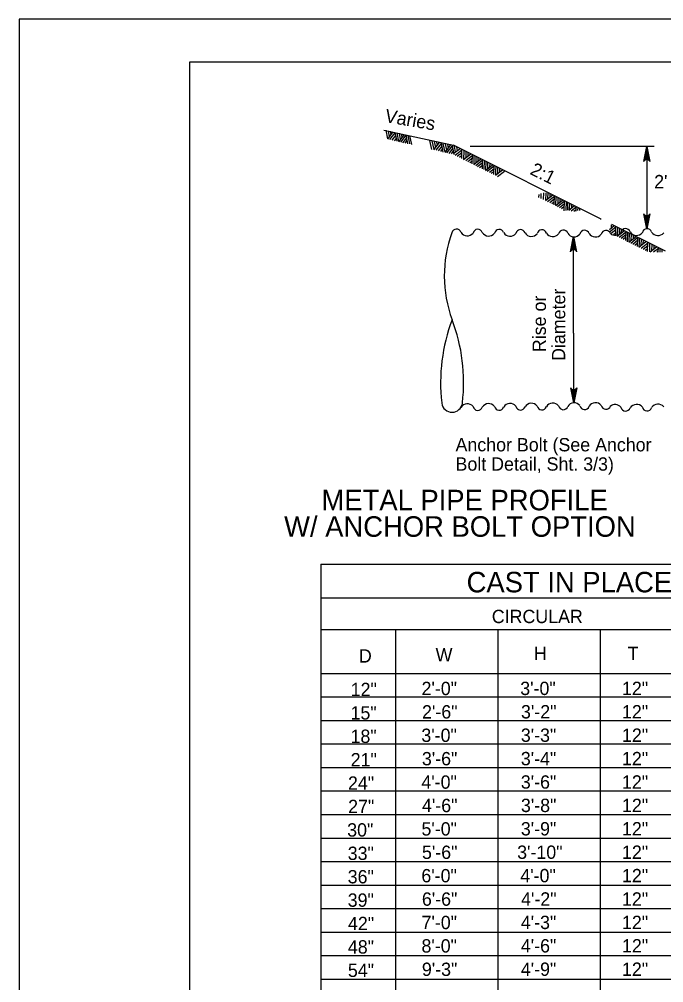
# Model space of a CAD drawing. Extents: x 1083.1 to 1117.1, y 675.4 to 741.4.
# Drawn here: x 1083.13 to 1090.68, y 730.07 to 741.35 of the extents above; entities that cross this region are included whole.
import ezdxf

# ---------------------------------------------------------------- set-up
doc = ezdxf.new("R2010")
doc.units = 0
doc.layers.add('Level 1', color=7, linetype='Continuous')

msp = doc.modelspace()

# ---------------------------------------------------------------- linework, layer by layer
at = {"layer": 'Level 1'}
for p, q in [((1087.399, 740.054), (1088.214, 739.88)), ((1087.444, 739.953), (1087.423, 740.054)), ((1087.443, 739.951), (1087.508, 740.035)), ((1087.465, 739.979), (1087.45, 740.048)), ((1087.469, 739.945), (1087.531, 740.025)), ((1087.483, 740.004), (1087.476, 740.042)), ((1087.552, 739.925), (1087.53, 740.03)), ((1087.574, 739.923), (1087.553, 740.024)), ((1087.572, 739.921), (1087.638, 740.005)), ((1087.593, 739.948), (1087.579, 740.019)), ((1087.613, 739.973), (1087.605, 740.012)), ((1087.495, 739.938), (1087.538, 739.993)), ((1087.523, 739.932), (1087.545, 739.96)), ((1087.596, 739.915), (1087.659, 739.997)), ((1087.621, 739.909), (1087.665, 739.967)), ((1087.646, 739.904), (1087.672, 739.937)), ((1087.68, 739.896), (1087.659, 740)), ((1087.703, 739.894), (1087.682, 739.995)), ((1087.724, 739.889), (1087.702, 739.99)), ((1087.96, 739.831), (1087.937, 739.936)), ((1087.986, 739.828), (1087.965, 739.929)), ((1087.984, 739.826), (1088.049, 739.91)), ((1088.006, 739.854), (1087.992, 739.923)), ((1088.01, 739.82), (1088.072, 739.9)), ((1088.025, 739.879), (1088.017, 739.917)), ((1088.094, 739.8), (1088.071, 739.905)), ((1088.116, 739.798), (1088.094, 739.899)), ((1088.135, 739.823), (1088.12, 739.894)), ((1088.037, 739.813), (1088.079, 739.868)), ((1088.065, 739.807), (1088.086, 739.835)), ((1088.114, 739.796), (1088.179, 739.88)), ((1088.137, 739.79), (1088.2, 739.872)), ((1088.154, 739.848), (1088.146, 739.887)), ((1088.163, 739.784), (1088.207, 739.842)), ((1088.188, 739.779), (1088.213, 739.812)), ((1088.222, 739.771), (1088.2, 739.875)), ((1089.944, 739.015), (1088.214, 739.88)), ((1088.219, 739.785), (1088.29, 739.842)), ((1088.238, 739.8), (1088.224, 739.87)), ((1088.233, 739.762), (1088.312, 739.826)), ((1088.262, 739.819), (1088.254, 739.86)), ((1088.257, 739.75), (1088.312, 739.793)), ((1088.31, 739.724), (1088.312, 739.831)), ((1088.332, 739.713), (1088.415, 739.779)), ((1088.334, 739.714), (1088.337, 739.818)), ((1088.36, 739.735), (1088.362, 739.806)), ((1088.384, 739.755), (1088.385, 739.794)), ((1090.562, 739.865), (1088.41, 739.865)), ((1090.454, 739.703), (1090.478, 739.865)), ((1090.464, 739.709), (1090.478, 739.865)), ((1090.478, 739.865), (1090.478, 738.9)), ((1090.478, 739.712), (1090.478, 739.865)), ((1090.49, 739.71), (1090.478, 739.865)), ((1090.501, 739.705), (1090.478, 739.865)), ((1088.282, 739.738), (1088.311, 739.761)), ((1088.356, 739.701), (1088.435, 739.764)), ((1088.381, 739.688), (1088.435, 739.732)), ((1088.406, 739.676), (1088.434, 739.698)), ((1088.433, 739.662), (1088.436, 739.769)), ((1088.451, 739.653), (1088.534, 739.72)), ((1088.454, 739.655), (1088.457, 739.759)), ((1088.473, 739.642), (1088.553, 739.707)), ((1088.478, 739.674), (1088.48, 739.747)), ((1088.496, 739.631), (1088.553, 739.676)), ((1088.503, 739.694), (1088.504, 739.735)), ((1088.551, 739.603), (1088.554, 739.71)), ((1088.572, 739.595), (1088.575, 739.699)), ((1088.591, 739.587), (1088.594, 739.69)), ((1088.615, 739.606), (1088.617, 739.678)), ((1088.64, 739.626), (1088.641, 739.666)), ((1088.519, 739.619), (1088.552, 739.646)), ((1088.588, 739.585), (1088.671, 739.651)), ((1088.609, 739.574), (1088.69, 739.639)), ((1088.633, 739.562), (1088.689, 739.607)), ((1088.656, 739.551), (1088.689, 739.577)), ((1088.687, 739.535), (1088.691, 739.642)), ((1088.704, 739.527), (1088.787, 739.593)), ((1088.709, 739.531), (1088.71, 739.581)), ((1088.71, 739.581), (1088.712, 739.631)), ((1088.73, 739.514), (1088.809, 739.577)), ((1088.731, 739.549), (1088.733, 739.62)), ((1088.755, 739.568), (1088.757, 739.608)), ((1089.214, 739.269), (1089.215, 739.301)), ((1089.241, 739.256), (1089.242, 739.314)), ((1089.267, 739.245), (1089.27, 739.321)), ((1089.292, 739.233), (1089.375, 739.299)), ((1089.294, 739.235), (1089.297, 739.322)), ((1089.316, 739.221), (1089.395, 739.284)), ((1089.32, 739.255), (1089.322, 739.32)), ((1089.34, 739.209), (1089.394, 739.252)), ((1089.344, 739.275), (1089.345, 739.314)), ((1089.366, 739.196), (1089.393, 739.218)), ((1089.393, 739.183), (1089.395, 739.289)), ((1089.411, 739.173), (1089.494, 739.24)), ((1089.413, 739.175), (1089.417, 739.279)), ((1089.432, 739.163), (1089.513, 739.227)), ((1089.438, 739.195), (1089.44, 739.267)), ((1089.463, 739.215), (1089.464, 739.255)), ((1089.51, 739.111), (1089.513, 739.23)), ((1089.532, 739.116), (1089.535, 739.219)), ((1089.456, 739.151), (1089.512, 739.196)), ((1089.479, 739.139), (1089.511, 739.166)), ((1089.551, 739.119), (1089.553, 739.21)), ((1089.565, 739.119), (1089.631, 739.172)), ((1089.574, 739.126), (1089.577, 739.198)), ((1089.591, 739.112), (1089.65, 739.159)), ((1089.6, 739.146), (1089.601, 739.187)), ((1089.624, 739.108), (1089.649, 739.128)), ((1089.649, 739.109), (1089.65, 739.162)), ((1089.671, 739.114), (1089.672, 739.151)), ((1089.692, 739.116), (1089.693, 739.14)), ((1089.94, 739.009), (1089.94, 739.017)), ((1090.456, 739.061), (1090.478, 738.9)), ((1090.467, 739.055), (1090.478, 738.9)), ((1090.503, 739.063), (1090.478, 738.9)), ((1090.493, 739.056), (1090.478, 738.9)), ((1090.478, 739.054), (1090.478, 738.9)), ((1090.039, 738.894), (1090.096, 738.939)), ((1090.04, 738.864), (1090.116, 738.924)), ((1090.041, 738.895), (1090.041, 738.897)), ((1090.041, 738.897), (1090.041, 738.897)), ((1090.061, 738.848), (1090.115, 738.891)), ((1090.064, 738.915), (1090.066, 738.947)), ((1090.066, 738.947), (1090.066, 738.947)), ((1090.698, 738.638), (1090.069, 738.953)), ((1090.113, 738.822), (1090.116, 738.929)), ((1090.131, 738.813), (1090.215, 738.88)), ((1090.134, 738.815), (1090.137, 738.918)), ((1090.158, 738.834), (1090.16, 738.907)), ((1090.183, 738.854), (1090.185, 738.895)), ((1089.595, 738.648), (1089.62, 738.81)), ((1089.606, 738.654), (1089.62, 738.81)), ((1089.62, 738.657), (1089.62, 738.81)), ((1089.631, 738.655), (1089.62, 738.81)), ((1089.642, 738.65), (1089.62, 738.81)), ((1089.62, 737.68), (1089.62, 738.807)), ((1090.086, 738.836), (1090.114, 738.858)), ((1090.153, 738.802), (1090.234, 738.867)), ((1090.177, 738.791), (1090.233, 738.836)), ((1090.199, 738.779), (1090.232, 738.805)), ((1090.231, 738.763), (1090.234, 738.87)), ((1090.252, 738.748), (1090.255, 738.854)), ((1090.268, 738.745), (1090.352, 738.811)), ((1090.271, 738.747), (1090.274, 738.85)), ((1090.29, 738.734), (1090.37, 738.798)), ((1090.295, 738.766), (1090.297, 738.838)), ((1090.313, 738.722), (1090.37, 738.767)), ((1090.32, 738.786), (1090.322, 738.826)), ((1090.368, 738.695), (1090.371, 738.801)), ((1090.391, 738.741), (1090.392, 738.791)), ((1090.412, 738.708), (1090.414, 738.78)), ((1090.436, 738.728), (1090.437, 738.768)), ((1090.336, 738.711), (1090.369, 738.737)), ((1090.384, 738.687), (1090.468, 738.753)), ((1090.389, 738.691), (1090.391, 738.741)), ((1090.41, 738.674), (1090.49, 738.737)), ((1090.435, 738.661), (1090.489, 738.704)), ((1090.459, 738.649), (1090.488, 738.672)), ((1090.487, 738.635), (1090.49, 738.742)), ((1090.512, 738.631), (1090.515, 738.73)), ((1090.518, 738.631), (1090.593, 738.69)), ((1090.538, 738.647), (1090.54, 738.717)), ((1090.555, 738.63), (1090.613, 738.675)), ((1090.562, 738.666), (1090.563, 738.705)), ((1090.612, 738.628), (1090.613, 738.68)), ((1090.633, 738.627), (1090.634, 738.67)), ((1090.657, 738.627), (1090.658, 738.658)), ((1090.594, 738.629), (1090.612, 738.643)), ((1089.62, 737.68), (1089.62, 736.862)), ((1089.6, 737.022), (1089.622, 736.862)), ((1089.611, 737.017), (1089.622, 736.862)), ((1089.647, 737.024), (1089.622, 736.862)), ((1089.636, 737.018), (1089.622, 736.862)), ((1089.622, 737.015), (1089.622, 736.862)), ((1086.66, 734.976), (1086.654, 720.144)), ((1086.66, 734.976), (1103.868, 734.976)), ((1103.868, 734.576), (1086.654, 734.576)), ((1103.868, 734.205), (1086.654, 734.205)), ((1087.536, 721.026), (1087.536, 734.205)), ((1088.735, 721.026), (1088.735, 734.205)), ((1089.935, 721.026), (1089.935, 734.205)), ((1103.868, 733.692), (1086.654, 733.692)), ((1103.868, 733.692), (1086.689, 733.692)), ((1103.868, 733.416), (1086.654, 733.416)), ((1103.868, 733.141), (1086.654, 733.141)), ((1103.868, 732.865), (1086.654, 732.865)), ((1103.868, 732.59), (1086.654, 732.59)), ((1103.868, 732.315), (1086.654, 732.315)), ((1103.868, 732.039), (1086.654, 732.039)), ((1103.868, 731.764), (1086.654, 731.764)), ((1103.868, 731.489), (1086.654, 731.489)), ((1103.868, 731.213), (1086.654, 731.213)), ((1097.894, 730.938), (1086.654, 730.938)), ((1097.894, 730.663), (1086.654, 730.663)), ((1103.868, 730.387), (1086.654, 730.387)), ((1091.981, 730.112), (1086.654, 730.112))]:
    msp.add_line(p, q, dxfattribs=at)
for points in [[(1083.126, 719.354), (1117.126, 719.354), (1117.126, 741.354), (1083.126, 741.354)], [(1085.126, 740.854), (1116.626, 740.854), (1116.626, 719.854), (1085.126, 719.854)]]:
    msp.add_lwpolyline(points, close=True, dxfattribs=at)
for points in [[(1090.443, 739.688), (1090.478, 739.865), (1090.514, 739.688)], [(1090.514, 739.077), (1090.478, 738.9), (1090.443, 739.077)], [(1089.585, 738.633), (1089.62, 738.81), (1089.655, 738.633)], [(1089.657, 737.039), (1089.622, 736.862), (1089.587, 737.039)]]:
    msp.add_lwpolyline(points, dxfattribs=at)
for centre, start, end in [((1090.478, 739.674), 22.0878, 157.9139), ((1090.478, 739.092), 202.0878, 337.9139), ((1089.62, 738.619), 22.0878, 157.9139), ((1089.622, 737.054), 202.0878, 337.9139)]:
    msp.add_arc(centre, 0.0382, start, end, dxfattribs=at)
for centre, major_axis, start_param, end_param in [((1088.248, 738.841), (0.056, 0), 0.338176, 2.886862), ((1088.498, 738.839), (0.056, 0), 0.338176, 2.936471), ((1088.748, 738.837), (0.056, 0), 0.338176, 2.936471), ((1088.998, 738.835), (0.056, 0), 0.338176, 2.936471), ((1089.248, 738.833), (0.056, 0), 0.338176, 2.936471), ((1089.499, 738.83), (0.056, 0), 0.338176, 2.936471), ((1089.749, 738.828), (0.056, 0), 0.338176, 2.936471), ((1089.999, 738.826), (0.056, 0), 0.338176, 2.936471), ((1090.23, 738.847), (0.056, 0), 0.338176, 2.936471), ((1090.481, 738.845), (0.056, 0), 0.338176, 2.936471), ((1089.598, 738.35), (-1.493, 0), 5.937722, 6.635502), ((1088.375, 738.906), (0.0877, 0), 3.693284, 5.600053), ((1088.625, 738.904), (0.0877, 0), 3.693284, 5.600053), ((1088.876, 738.902), (0.0877, 0), 3.693284, 5.600053), ((1089.126, 738.899), (0.0877, 0), 3.693284, 5.600053), ((1089.376, 738.897), (0.0877, 0), 3.693284, 5.600053), ((1089.626, 738.895), (0.0877, 0), 3.693284, 5.600053), ((1089.876, 738.893), (0.0877, 0), 3.693284, 5.600053), ((1090.107, 738.913), (0.0877, 0), 4.01572, 5.600053), ((1090.358, 738.911), (0.0877, 0), 3.693284, 5.600053), ((1090.608, 738.909), (0.0877, 0), 3.693284, 5.600053), ((1090.127, 737.101), (-2.065, 0), 5.919813, 6.398853), ((1086.267, 737.101), (2.065, 0), 6.167517, 6.646557), ((1088.197, 736.875), (-0.122, 0), 0.132192, 1.570796), ((1088.197, 736.875), (0.122, 0), 4.712389, 6.150994), ((1088.375, 736.764), (0.0877, 0), 0.683132, 2.589902), ((1088.625, 736.766), (0.0877, 0), 0.683132, 2.589902), ((1088.876, 736.768), (0.0877, 0), 0.683132, 2.589902), ((1089.126, 736.77), (0.0877, 0), 0.683132, 2.589902), ((1089.376, 736.772), (0.0877, 0), 0.683132, 2.589902), ((1089.626, 736.775), (0.0877, 0), 0.683132, 2.589902), ((1089.876, 736.777), (0.0877, 0), 0.683132, 2.589902), ((1090.107, 736.756), (0.0877, 0), 0.683132, 2.296456), ((1090.358, 736.758), (0.0877, 0), 0.683132, 2.589902), ((1090.608, 736.761), (0.0877, 0), 0.683132, 2.589902), ((1088.498, 736.83), (0.056, 0), 3.346714, 5.94501), ((1088.748, 736.833), (0.056, 0), 3.346714, 5.94501), ((1088.998, 736.835), (0.056, 0), 3.346714, 5.94501), ((1089.248, 736.837), (0.056, 0), 3.346714, 5.94501), ((1089.499, 736.839), (0.056, 0), 3.346714, 5.94501), ((1089.749, 736.841), (0.056, 0), 3.346714, 5.94501), ((1089.999, 736.844), (0.056, 0), 3.346714, 5.94501), ((1090.23, 736.823), (0.056, 0), 3.346714, 5.94501), ((1090.481, 736.825), (0.056, 0), 3.346714, 5.94501)]:
    msp.add_ellipse(centre, major_axis=major_axis, ratio=0.999895, start_param=start_param, end_param=end_param, dxfattribs=at)

# ---------------------------------------------------------------- texts
for s, rotation, p in [('Varies', 350.3559, (1087.402, 740.151)), ('2:1', 333.4374, (1089.099, 739.545)), ('Rise or', 90, (1089.296, 737.457)), ('Diameter', 90, (1089.522, 737.354))]:
    msp.add_text(s, height=0.156, rotation=rotation, dxfattribs=at).set_placement(p)
for s, height, p in [("2' [600] recommended", 0.156, (1090.564, 739.375)), ('Anchor Bolt (See Anchor', 0.156, (1088.237, 736.295)), ('Bolt Detail, Sht. 3/3)', 0.156, (1088.237, 736.069)), ('METAL PIPE PROFILE', 0.24, (1086.667, 735.605)), ('W/ ANCHOR BOLT OPTION', 0.24, (1086.229, 735.295)), ('CAST IN PLACE HW FOR CORRUGATED METAL PIPE & PLASTIC PIPE (English)', 0.24, (1088.367, 734.644)), ('CIRCULAR', 0.156, (1088.662, 734.284)), ('D', 0.156, (1087.105, 733.822)), ('W', 0.156, (1088.004, 733.835)), ('H', 0.156, (1089.154, 733.851)), ('T', 0.156, (1090.253, 733.851)), ('12"', 0.156, (1087.009, 733.429)), ('2\'-0"', 0.156, (1087.839, 733.441)), ('3\'-0"', 0.156, (1088.995, 733.442)), ('12"', 0.156, (1090.187, 733.442)), ('15"', 0.156, (1087.007, 733.155)), ('2\'-6"', 0.156, (1087.845, 733.167)), ('3\'-2"', 0.156, (1089.004, 733.168)), ('12"', 0.156, (1090.187, 733.168)), ('18"', 0.156, (1087.007, 732.881)), ('3\'-0"', 0.156, (1087.837, 732.893)), ('3\'-3"', 0.156, (1089.002, 732.894)), ('12"', 0.156, (1090.187, 732.894)), ('21"', 0.156, (1087.009, 732.607)), ('3\'-6"', 0.156, (1087.843, 732.619)), ('3\'-4"', 0.156, (1089.002, 732.62)), ('12"', 0.156, (1090.187, 732.62)), ('24"', 0.156, (1086.977, 732.333)), ('4\'-0"', 0.156, (1087.837, 732.345)), ('3\'-6"', 0.156, (1089.002, 732.346)), ('12"', 0.156, (1090.187, 732.346)), ('4\'-6"', 0.156, (1087.844, 732.071)), ('3\'-8"', 0.156, (1089.003, 732.072)), ('12"', 0.156, (1090.187, 732.072)), ('27"', 0.156, (1086.979, 732.059)), ('30"', 0.156, (1086.968, 731.785)), ('5\'-0"', 0.156, (1087.838, 731.797)), ('3\'-9"', 0.156, (1089.002, 731.798)), ('12"', 0.156, (1090.187, 731.798)), ('33"', 0.156, (1086.974, 731.511)), ('5\'-6"', 0.156, (1087.844, 731.523)), ('3\'-10"', 0.156, (1088.959, 731.524)), ('12"', 0.156, (1090.187, 731.524)), ('36"', 0.156, (1086.974, 731.237)), ('6\'-0"', 0.156, (1087.837, 731.249)), ('4\'-0"', 0.156, (1088.996, 731.25)), ('12"', 0.156, (1090.187, 731.25)), ('39"', 0.156, (1086.974, 730.963)), ('6\'-6"', 0.156, (1087.843, 730.975)), ('4\'-2"', 0.156, (1089.005, 730.976)), ('12"', 0.156, (1090.187, 730.976)), ('42"', 0.156, (1086.977, 730.689)), ('7\'-0"', 0.156, (1087.839, 730.701)), ('4\'-3"', 0.156, (1089.002, 730.702)), ('12"', 0.156, (1090.187, 730.702)), ('48"', 0.156, (1086.976, 730.415)), ('8\'-0"', 0.156, (1087.838, 730.427)), ('4\'-6"', 0.156, (1089.002, 730.428)), ('12"', 0.156, (1090.187, 730.428)), ('9\'-3"', 0.156, (1087.843, 730.153)), ('4\'-9"', 0.156, (1089.002, 730.154)), ('12"', 0.156, (1090.187, 730.154)), ('54"', 0.156, (1086.976, 730.141))]:
    msp.add_text(s, height=height, dxfattribs=at).set_placement(p)

doc.saveas('drawing.dxf')
